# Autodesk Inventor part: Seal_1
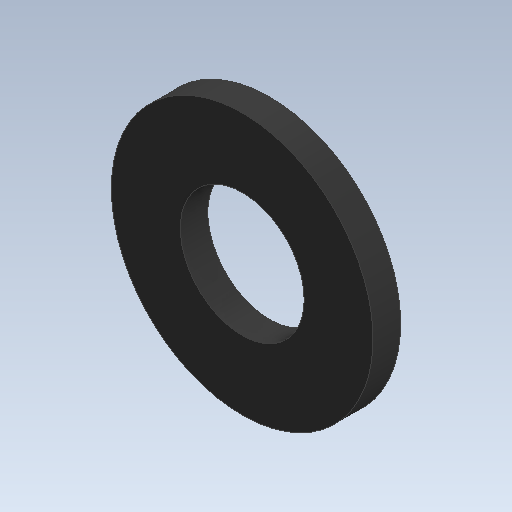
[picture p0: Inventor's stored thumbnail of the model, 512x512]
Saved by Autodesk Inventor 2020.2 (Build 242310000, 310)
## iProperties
Created: 2019-12
Part Number: Seal_1
Material: Rubber
Document SubType Name: Modeling
Designer: Synergysoft Dell02
Density: 0.93 g/cm^3
Appearance: Rubber - Black
Author: Synergysoft Dell02
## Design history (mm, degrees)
sketch "Sketch1"
  geometry: C1 r 9 at (0, 0) reference; C2 r 19 at (0, 0) reference; 1 further point
  node "Reference1"
workplane "Work Plane1"
extrude "Extrusion1" new body sketch "Sketch1" stored distance "d0" = 10; taper "d1" = 0 deg
body "Solid1"
